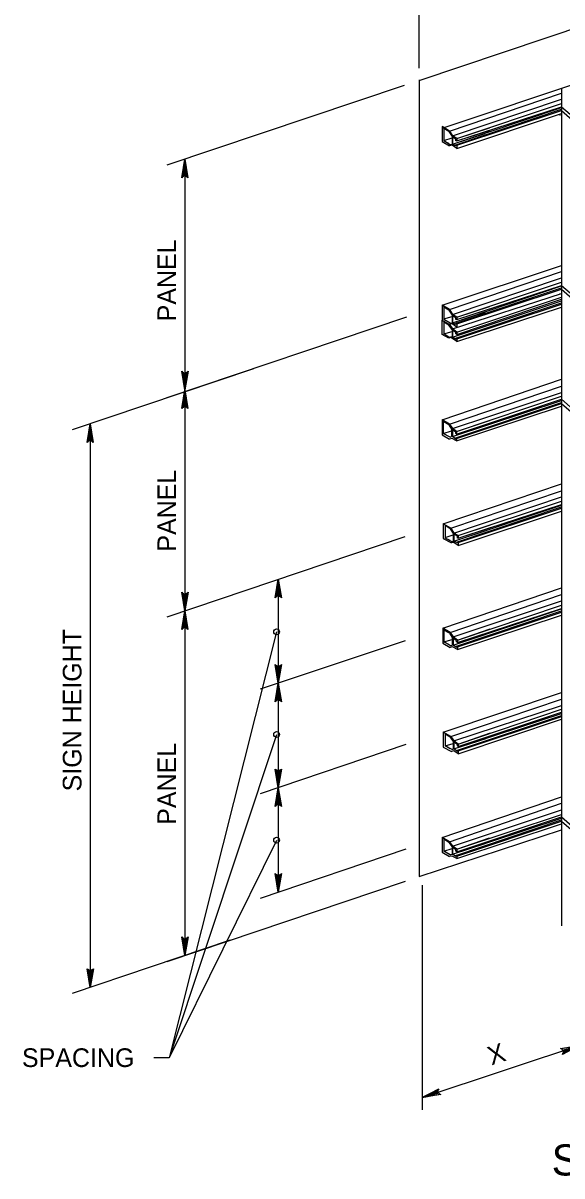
# Model space of a CAD drawing. Extents: x 650495 to 651400, y 297864 to 299646.
# Drawn here: x 650741.8 to 650828.3, y 299357.5 to 299542.7 of the extents above; entities that cross this region are included whole.
import ezdxf

# ---------------------------------------------------------------- set-up
doc = ezdxf.new("R2010")
doc.units = 0
doc.layers.add('2', color=7, linetype='Continuous')
doc.layers.add('3', color=7, linetype='Continuous')

# ---------------------------------------------------------------- blocks, each defined once
blk = doc.blocks.new('RARROW')
at = {"layer": '3'}
blk.add_lwpolyline([(-2.2695, 0.285), (-2.184875, 0.12075), (0, 0), (-2.2695, 0.285), (-2.38575, 0.384625), (0, 0), (-2.183125, -0.108), (-2.262875, -0.2705), (0, 0), (-2.38575, -0.379125), (-2.262875, -0.2705)], dxfattribs=at)

msp = doc.modelspace()

# ---------------------------------------------------------------- linework, layer by layer
at = {"layer": '2'}
for p, q in [((650805.4, 299533.47), (650908.3, 299568.07)), ((650805.4, 299535.47), (650805.4, 299567.07)), ((650809.3, 299525.87), (650904, 299557.67)), ((650803, 299532.67), (650764.9, 299519.87)), ((650805.4, 299533.57), (650805.4, 299405.57)), ((650828.3, 299532.27), (650828.3, 299397.67)), ((650810.3, 299525.37), (650828.3, 299531.47)), ((650810.8, 299524.57), (650828.3, 299530.47)), ((650810.8, 299523.27), (650828.3, 299529.17)), ((650811.3, 299523.17), (650828.3, 299528.87)), ((650811.5, 299524.17), (650828.3, 299529.77)), ((650811.5, 299523.77), (650828.3, 299529.27)), ((650811.5, 299523.07), (650828.3, 299528.67)), ((650828.3, 299529.27), (650832.8, 299525.37)), ((650828.3, 299528.67), (650832.8, 299524.67)), ((650811.5, 299522.57), (650828.3, 299528.17)), ((650828, 299527.97), (650828, 299527.87)), ((650828.3, 299528.17), (650828.3, 299528.17)), ((650809.1, 299526.07), (650809.1, 299526.07)), ((650810.3, 299525.37), (650809.1, 299526.07)), ((650809.1, 299526.07), (650809.1, 299523.67)), ((650809.1, 299526.07), (650810.3, 299525.37)), ((650809.4, 299525.77), (650809.4, 299523.77)), ((650810.2, 299525.27), (650809.4, 299525.77)), ((650810.2, 299525.27), (650810.7, 299524.47)), ((650810.3, 299525.37), (650810.8, 299524.57)), ((650810.8, 299523.27), (650816, 299524.97)), ((650811.5, 299524.17), (650816.7, 299525.87)), ((650811.5, 299523.77), (650816.7, 299525.47)), ((650809.1, 299523.67), (650810.3, 299522.97)), ((650809.4, 299523.87), (650810.7, 299524.27)), ((650810.4, 299523.17), (650809.4, 299523.77)), ((650810.2, 299523.37), (650809.4, 299523.77)), ((650810.7, 299523.07), (650810.3, 299522.97)), ((650810.4, 299523.17), (650810.7, 299523.27)), ((650810.7, 299524.57), (650810.7, 299523.27)), ((650811.5, 299522.57), (650810.7, 299523.07)), ((650811.5, 299524.17), (650810.8, 299524.57)), ((650811.3, 299524.07), (650810.8, 299524.37)), ((650811.3, 299524.07), (650810.8, 299524.37)), ((650810.8, 299524.37), (650810.8, 299523.27)), ((650811.3, 299522.97), (650810.8, 299523.27)), ((650811.3, 299524.07), (650811.3, 299523.87)), ((650811.3, 299523.77), (650811.3, 299524.07)), ((650811.5, 299523.77), (650811.3, 299523.87)), ((650811.5, 299523.77), (650811.3, 299523.77)), ((650811.3, 299523.17), (650811.3, 299522.97)), ((650811.5, 299523.07), (650811.3, 299523.17)), ((650811.3, 299523.17), (650811.3, 299522.97)), ((650811.5, 299523.07), (650811.3, 299523.17)), ((650811.5, 299524.17), (650811.5, 299523.77)), ((650811.5, 299524.17), (650811.5, 299523.77)), ((650811.5, 299523.07), (650811.5, 299522.57)), ((650811.5, 299523.07), (650811.5, 299522.57)), ((650767.8, 299520.87), (650767.8, 299512.47)), ((650767.8, 299520.87), (650767.8, 299483.77)), ((650809.1, 299497.37), (650828.3, 299503.77)), ((650810.3, 299496.67), (650828.3, 299502.77)), ((650810.8, 299495.87), (650828.3, 299501.77)), ((650811.5, 299495.47), (650828.3, 299501.07)), ((650810.8, 299494.57), (650828.3, 299500.47)), ((650810.8, 299493.57), (650828.3, 299499.27)), ((650811.3, 299494.47), (650828.3, 299500.17)), ((650811.5, 299495.07), (650828.3, 299500.57)), ((650811.5, 299494.37), (650828.3, 299499.97)), ((650828, 299499.27), (650828, 299499.17)), ((650828.3, 299500.57), (650832.8, 299496.67)), ((650828.3, 299499.97), (650832.8, 299495.97)), ((650828.3, 299499.47), (650828.3, 299499.47)), ((650810.3, 299496.67), (650809.1, 299497.37)), ((650809.1, 299497.37), (650809.1, 299494.97)), ((650809.1, 299497.37), (650810.3, 299496.67)), ((650809.4, 299497.07), (650809.4, 299495.07)), ((650810.2, 299496.57), (650809.4, 299497.07)), ((650810.8, 299492.27), (650828.3, 299498.07)), ((650811.3, 299492.07), (650828.3, 299497.77)), ((650811.5, 299493.07), (650828.3, 299498.67)), ((650811.5, 299492.67), (650828.3, 299498.37)), ((650811.5, 299491.97), (650828.3, 299497.57)), ((650811.5, 299495.47), (650816.7, 299497.17)), ((650811.5, 299491.57), (650828.3, 299497.07)), ((650803.4, 299495.47), (650764.9, 299482.47)), ((650809.4, 299495.17), (650810.7, 299495.57)), ((650810.2, 299496.57), (650810.7, 299495.77)), ((650810.3, 299496.67), (650810.8, 299495.87)), ((650810.7, 299495.87), (650810.7, 299494.57)), ((650810.8, 299494.57), (650816, 299496.27)), ((650811.5, 299495.47), (650810.8, 299495.87)), ((650811.3, 299495.37), (650810.8, 299495.67)), ((650811.3, 299495.37), (650810.8, 299495.67)), ((650810.8, 299495.67), (650810.8, 299494.57)), ((650811.3, 299495.37), (650811.3, 299495.17)), ((650811.3, 299495.07), (650811.3, 299495.37)), ((650811.5, 299495.07), (650811.3, 299495.17)), ((650811.5, 299495.07), (650816.7, 299496.77)), ((650811.5, 299495.47), (650811.5, 299495.07)), ((650811.5, 299495.47), (650811.5, 299495.07)), ((650809.1, 299492.67), (650809.1, 299494.97)), ((650809.1, 299494.97), (650810.3, 299494.27)), ((650810.4, 299494.47), (650809.4, 299495.07)), ((650810.2, 299494.67), (650809.4, 299495.07)), ((650809.4, 299494.67), (650809.4, 299492.77)), ((650810.2, 299494.17), (650809.4, 299494.67)), ((650810.7, 299493.47), (650810.2, 299494.17)), ((650810.7, 299494.37), (650810.3, 299494.27)), ((650810.3, 299494.27), (650810.8, 299493.57)), ((650810.4, 299494.47), (650810.7, 299494.57)), ((650810.5, 299493.87), (650810.5, 299493.87)), ((650811.5, 299493.87), (650810.7, 299494.37)), ((650810.7, 299493.47), (650810.7, 299492.37)), ((650811.3, 299494.27), (650810.8, 299494.57)), ((650811.5, 299493.07), (650810.8, 299493.57)), ((650811.3, 299492.97), (650810.8, 299493.37)), ((650810.8, 299493.37), (650810.8, 299492.27)), ((650811.5, 299495.07), (650811.3, 299495.07)), ((650811.3, 299494.47), (650811.3, 299494.27)), ((650811.5, 299494.37), (650811.3, 299494.47)), ((650811.3, 299494.47), (650811.3, 299494.27)), ((650811.5, 299494.37), (650811.3, 299494.47)), ((650811.5, 299494.37), (650811.5, 299493.87)), ((650811.5, 299494.37), (650811.5, 299493.87)), ((650810.2, 299492.07), (650809.1, 299492.67)), ((650809.4, 299492.77), (650810.7, 299493.17)), ((650810.2, 299492.27), (650809.4, 299492.77)), ((650810.2, 299492.27), (650810.7, 299492.37)), ((650810.5, 299492.17), (650810.2, 299492.07)), ((650811.5, 299491.57), (650810.5, 299492.17)), ((650811.3, 299491.87), (650810.8, 299492.27)), ((650811.3, 299492.77), (650811.3, 299492.97)), ((650811.5, 299492.67), (650811.3, 299492.77)), ((650811.3, 299492.07), (650811.3, 299491.87)), ((650811.5, 299491.97), (650811.3, 299492.07)), ((650811.5, 299493.07), (650811.5, 299492.67)), ((650811.5, 299491.97), (650811.5, 299491.57)), ((650778.8, 299487.17), (650749.7, 299477.37)), ((650809.1, 299478.97), (650828.3, 299485.47)), ((650810.3, 299478.27), (650828.3, 299484.37)), ((650767.8, 299483.77), (650767.8, 299437.57)), ((650810.8, 299477.57), (650828.3, 299483.37)), ((650811.4, 299477.07), (650828.3, 299482.77)), ((650811.4, 299476.67), (650828.3, 299482.27)), ((650828.3, 299482.27), (650832.8, 299478.27)), ((650810.8, 299476.27), (650828.3, 299482.07)), ((650811.3, 299476.07), (650828.3, 299481.77)), ((650811.4, 299475.97), (650828.3, 299481.57)), ((650811.4, 299475.57), (650828.3, 299481.17)), ((650828.3, 299481.57), (650832.8, 299477.67)), ((650809.1, 299478.97), (650809.1, 299478.97)), ((650810.3, 299478.27), (650809.1, 299478.97)), ((650809.1, 299478.97), (650809.1, 299476.57)), ((650809.1, 299478.97), (650810.3, 299478.27)), ((650809.3, 299478.67), (650809.3, 299476.77)), ((650810.2, 299478.17), (650809.3, 299478.67)), ((650811.4, 299477.07), (650816.7, 299478.87)), ((650752.6, 299478.34), (650752.6, 299432.37)), ((650809.1, 299476.57), (650810.3, 299475.87)), ((650809.3, 299476.77), (650810.6, 299477.17)), ((650810.4, 299476.17), (650809.3, 299476.77)), ((650810.2, 299476.27), (650809.3, 299476.77)), ((650810.2, 299478.17), (650810.6, 299477.47)), ((650810.3, 299478.27), (650810.8, 299477.57)), ((650810.6, 299477.47), (650810.6, 299476.27)), ((650810.8, 299476.27), (650815.9, 299477.97)), ((650811.4, 299477.07), (650810.8, 299477.57)), ((650811.3, 299476.97), (650810.8, 299477.37)), ((650811.3, 299476.97), (650810.8, 299477.37)), ((650810.8, 299477.37), (650810.8, 299476.27)), ((650811.3, 299476.97), (650811.3, 299476.77)), ((650811.3, 299476.77), (650811.3, 299476.97)), ((650811.4, 299476.67), (650811.3, 299476.77)), ((650811.4, 299476.67), (650811.3, 299476.77)), ((650811.4, 299476.67), (650816.7, 299478.37)), ((650811.4, 299477.07), (650811.4, 299476.67)), ((650811.4, 299477.07), (650811.4, 299476.67)), ((650810.7, 299475.97), (650810.3, 299475.87)), ((650810.4, 299476.17), (650810.6, 299476.27)), ((650811.4, 299475.57), (650810.7, 299475.97)), ((650811.3, 299475.87), (650810.8, 299476.27)), ((650811.3, 299476.07), (650811.3, 299475.87)), ((650811.4, 299475.97), (650811.3, 299476.07)), ((650811.3, 299476.07), (650811.3, 299475.87)), ((650811.4, 299475.97), (650811.3, 299476.07)), ((650811.4, 299475.97), (650811.4, 299475.57)), ((650811.4, 299475.97), (650811.4, 299475.57)), ((650809.3, 299462.27), (650828.3, 299468.67)), ((650810.5, 299461.57), (650828.3, 299467.57)), ((650811, 299460.77), (650828.3, 299466.57)), ((650811.7, 299460.37), (650828.3, 299465.87)), ((650811, 299459.47), (650828.3, 299465.27)), ((650811.6, 299459.37), (650828.3, 299464.97)), ((650811.7, 299459.97), (650828.3, 299465.37)), ((650811.7, 299459.27), (650828.3, 299464.77)), ((650811.7, 299458.77), (650828.3, 299464.27)), ((650809.3, 299462.27), (650809.3, 299462.27)), ((650810.5, 299461.57), (650809.3, 299462.27)), ((650809.3, 299462.27), (650809.3, 299459.87)), ((650809.3, 299462.27), (650810.5, 299461.57)), ((650809.6, 299461.97), (650809.6, 299459.97)), ((650810.4, 299461.47), (650809.6, 299461.97)), ((650811.7, 299460.37), (650816.9, 299462.07)), ((650803.1, 299460.17), (650764.9, 299447.27)), ((650809.6, 299460.07), (650810.9, 299460.47)), ((650810.7, 299459.37), (650809.6, 299459.97)), ((650810.4, 299459.57), (650809.6, 299459.97)), ((650810.4, 299461.47), (650810.9, 299460.67)), ((650810.5, 299461.57), (650811, 299460.77)), ((650810.9, 299460.77), (650810.9, 299459.47)), ((650811, 299459.47), (650816.2, 299461.17)), ((650811.7, 299460.37), (650811, 299460.77)), ((650811.6, 299460.27), (650811, 299460.57)), ((650811.6, 299460.27), (650811, 299460.57)), ((650811, 299460.57), (650811, 299459.47)), ((650811.6, 299460.27), (650811.6, 299460.07)), ((650811.6, 299459.97), (650811.6, 299460.27)), ((650811.7, 299459.97), (650811.6, 299460.07)), ((650811.7, 299459.97), (650811.6, 299459.97)), ((650811.7, 299459.97), (650816.9, 299461.67)), ((650811.7, 299460.37), (650811.7, 299459.97)), ((650811.7, 299460.37), (650811.7, 299459.97)), ((650809.3, 299459.87), (650810.6, 299459.17)), ((650811, 299459.27), (650810.6, 299459.17)), ((650810.7, 299459.37), (650810.9, 299459.47)), ((650811.6, 299459.17), (650811, 299459.47)), ((650811.7, 299458.77), (650811, 299459.27)), ((650811.6, 299459.37), (650811.6, 299459.17)), ((650811.7, 299459.27), (650811.6, 299459.37)), ((650811.6, 299459.37), (650811.6, 299459.17)), ((650811.7, 299459.27), (650811.6, 299459.37)), ((650811.7, 299459.27), (650811.7, 299458.77)), ((650811.7, 299459.27), (650811.7, 299458.77)), ((650782.8, 299453.37), (650782.8, 299424.17)), ((650782.8, 299453.31), (650782.8, 299403.07)), ((650809.2, 299445.47), (650828.3, 299451.97)), ((650810.4, 299444.77), (650828.3, 299450.87)), ((650810.9, 299444.07), (650828.3, 299449.87)), ((650811.6, 299443.57), (650828.3, 299449.17)), ((650767.8, 299448.27), (650767.8, 299392.87)), ((650810.9, 299442.77), (650828.3, 299448.57)), ((650811.4, 299442.57), (650828.3, 299448.27)), ((650811.6, 299443.17), (650828.3, 299448.67)), ((650811.6, 299442.47), (650828.3, 299448.07)), ((650811.6, 299442.07), (650828.3, 299447.57)), ((650782.8, 299445.37), (650782.8, 299436.97)), ((650809.2, 299445.47), (650809.2, 299445.47)), ((650810.4, 299444.77), (650809.2, 299445.47)), ((650809.2, 299445.47), (650809.2, 299443.07)), ((650809.2, 299445.47), (650810.4, 299444.77)), ((650809.4, 299445.17), (650809.4, 299443.27)), ((650810.3, 299444.67), (650809.4, 299445.17)), ((650811.6, 299443.57), (650816.8, 299445.37)), ((650782.5, 299444.87), (650765.3, 299376.47)), ((650803.2, 299443.47), (650779.9, 299435.67)), ((650809.4, 299443.27), (650810.7, 299443.67)), ((650810.5, 299442.67), (650809.4, 299443.27)), ((650810.3, 299442.77), (650809.4, 299443.27)), ((650810.3, 299444.67), (650810.7, 299443.97)), ((650810.4, 299444.77), (650810.9, 299444.07)), ((650810.7, 299443.97), (650810.7, 299442.77)), ((650810.9, 299442.77), (650816, 299444.47)), ((650811.6, 299443.57), (650810.9, 299444.07)), ((650811.4, 299443.47), (650810.9, 299443.87)), ((650811.4, 299443.47), (650810.9, 299443.87)), ((650810.9, 299443.87), (650810.9, 299442.77)), ((650811.4, 299443.47), (650811.4, 299443.27)), ((650811.4, 299443.27), (650811.4, 299443.47)), ((650811.6, 299443.17), (650811.4, 299443.27)), ((650811.6, 299443.17), (650811.4, 299443.27)), ((650811.6, 299443.17), (650816.8, 299444.87)), ((650811.6, 299443.57), (650811.6, 299443.17)), ((650811.6, 299443.57), (650811.6, 299443.17)), ((650752.6, 299443.17), (650752.6, 299387.77)), ((650809.2, 299443.07), (650810.4, 299442.37)), ((650810.8, 299442.47), (650810.4, 299442.37)), ((650810.5, 299442.67), (650810.7, 299442.77)), ((650811.6, 299442.07), (650810.8, 299442.47)), ((650811.4, 299442.37), (650810.9, 299442.77)), ((650811.4, 299442.57), (650811.4, 299442.37)), ((650811.6, 299442.47), (650811.4, 299442.57)), ((650811.4, 299442.57), (650811.4, 299442.37)), ((650811.6, 299442.47), (650811.4, 299442.57)), ((650811.6, 299442.47), (650811.6, 299442.07)), ((650811.6, 299442.47), (650811.6, 299442.07)), ((650809.3, 299428.77), (650828.3, 299435.17)), ((650810.5, 299428.07), (650828.3, 299434.07)), ((650811, 299427.37), (650828.3, 299433.07)), ((650811.7, 299426.87), (650828.3, 299432.47)), ((650811, 299426.07), (650828.3, 299431.77)), ((650811.6, 299425.87), (650828.3, 299431.47)), ((650811.7, 299426.47), (650828.3, 299431.97)), ((650811.7, 299425.77), (650828.3, 299431.27)), ((650811.7, 299425.27), (650828.3, 299430.87)), ((650782.8, 299428.67), (650782.8, 299420.27)), ((650809.3, 299428.77), (650809.3, 299428.77)), ((650810.5, 299428.07), (650809.3, 299428.77)), ((650809.3, 299428.77), (650809.3, 299426.37)), ((650809.3, 299428.77), (650810.5, 299428.07)), ((650809.6, 299428.47), (650809.6, 299426.57)), ((650810.4, 299427.97), (650809.6, 299428.47)), ((650811.7, 299426.87), (650816.9, 299428.67)), ((650782.5, 299428.37), (650765.3, 299376.47)), ((650803.3, 299426.77), (650779.9, 299418.87)), ((650809.6, 299426.57), (650810.9, 299426.97)), ((650810.7, 299425.97), (650809.6, 299426.57)), ((650810.4, 299426.07), (650809.6, 299426.57)), ((650810.4, 299427.97), (650810.9, 299427.27)), ((650810.5, 299428.07), (650811, 299427.37)), ((650810.9, 299427.27), (650810.9, 299426.07)), ((650811, 299426.07), (650816.2, 299427.77)), ((650811.7, 299426.87), (650811, 299427.37)), ((650811.6, 299426.77), (650811, 299427.17)), ((650811.6, 299426.77), (650811, 299427.17)), ((650811, 299427.17), (650811, 299426.07)), ((650811.6, 299426.77), (650811.6, 299426.57)), ((650811.6, 299426.57), (650811.6, 299426.77)), ((650811.7, 299426.47), (650811.6, 299426.57)), ((650811.7, 299426.47), (650811.6, 299426.57)), ((650811.7, 299426.47), (650816.9, 299428.17)), ((650811.7, 299426.87), (650811.7, 299426.47)), ((650811.7, 299426.87), (650811.7, 299426.47)), ((650809.3, 299426.37), (650810.6, 299425.67)), ((650811, 299425.77), (650810.6, 299425.67)), ((650810.7, 299425.97), (650810.9, 299426.07)), ((650811.6, 299425.67), (650811, 299426.07)), ((650811.7, 299425.27), (650811, 299425.77)), ((650811.6, 299425.87), (650811.6, 299425.67)), ((650811.7, 299425.77), (650811.6, 299425.87)), ((650811.6, 299425.87), (650811.6, 299425.67)), ((650811.7, 299425.77), (650811.6, 299425.87)), ((650811.7, 299425.77), (650811.7, 299425.27)), ((650811.7, 299425.77), (650811.7, 299425.27)), ((650805.9, 299370.07), (650949.3, 299417.67)), ((650809.1, 299411.87), (650828.3, 299418.37)), ((650810.3, 299411.17), (650828.3, 299417.37)), ((650810.8, 299410.47), (650828.3, 299416.27)), ((650811.5, 299409.97), (650828.3, 299415.57)), ((650810.8, 299409.17), (650828.3, 299414.97)), ((650811.3, 299408.97), (650828.3, 299414.67)), ((650811.5, 299409.57), (650828.3, 299415.17)), ((650811.5, 299408.87), (650828.3, 299414.47)), ((650811.5, 299408.47), (650828.3, 299414.07)), ((650828.3, 299415.17), (650832.8, 299411.17)), ((650828.3, 299414.47), (650832.8, 299410.57)), ((650805.4, 299405.57), (650828.3, 299413.07)), ((650809.1, 299411.87), (650809.1, 299411.87)), ((650810.3, 299411.17), (650809.1, 299411.87)), ((650809.1, 299411.87), (650809.1, 299409.47)), ((650809.1, 299411.87), (650810.3, 299411.17)), ((650811.5, 299409.97), (650816.7, 299411.77)), ((650782.5, 299411.37), (650765.3, 299376.47)), ((650803.3, 299409.97), (650779.9, 299402.07)), ((650809.4, 299411.57), (650809.4, 299409.67)), ((650810.2, 299411.07), (650809.4, 299411.57)), ((650809.4, 299409.67), (650810.7, 299410.07)), ((650810.2, 299411.07), (650810.7, 299410.37)), ((650810.3, 299411.17), (650810.8, 299410.47)), ((650810.7, 299410.37), (650810.7, 299409.17)), ((650810.8, 299409.17), (650816, 299410.87)), ((650811.5, 299409.97), (650810.8, 299410.47)), ((650811.3, 299409.87), (650810.8, 299410.27)), ((650811.3, 299409.87), (650810.8, 299410.27)), ((650810.8, 299410.27), (650810.8, 299409.17)), ((650811.3, 299409.87), (650811.3, 299409.67)), ((650811.3, 299409.67), (650811.3, 299409.87)), ((650811.5, 299409.57), (650816.7, 299411.27)), ((650811.5, 299409.97), (650811.5, 299409.57)), ((650811.5, 299409.97), (650811.5, 299409.57)), ((650809.1, 299409.47), (650810.3, 299408.77)), ((650810.4, 299409.07), (650809.4, 299409.67)), ((650810.2, 299409.17), (650809.4, 299409.67)), ((650810.7, 299408.87), (650810.3, 299408.77)), ((650810.4, 299409.07), (650810.7, 299409.17)), ((650811.5, 299408.47), (650810.7, 299408.87)), ((650811.3, 299408.77), (650810.8, 299409.17)), ((650811.5, 299409.57), (650811.3, 299409.67)), ((650811.5, 299409.57), (650811.3, 299409.67)), ((650811.3, 299408.97), (650811.3, 299408.77)), ((650811.5, 299408.87), (650811.3, 299408.97)), ((650811.3, 299408.97), (650811.3, 299408.77)), ((650811.5, 299408.87), (650811.3, 299408.97)), ((650811.5, 299408.87), (650811.5, 299408.47)), ((650811.5, 299408.87), (650811.5, 299408.47)), ((650803.2, 299404.77), (650764.9, 299391.87)), ((650805.9, 299404.17), (650805.9, 299368.07)), ((650775.1, 299395.37), (650749.7, 299386.77)), ((650765.3, 299376.47), (650762.8, 299376.47)), ((650765.3, 299376.47), (650762.8, 299376.47)), ((650765.3, 299376.47), (650762.8, 299376.47))]:
    msp.add_line(p, q, dxfattribs=at)
for centre in [(650782.53, 299444.9), (650782.53, 299428.41), (650782.53, 299411.41)]:
    msp.add_circle(centre, 0.467, dxfattribs=at)

# ---------------------------------------------------------------- block references
for p, xscale, yscale, rotation in [((650767.8, 299520.87), 1.2574347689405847, 1.3092961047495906, 89.99999999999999), ((650767.8, 299483.77), 1.2574347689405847, 1.3092961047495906, -90.00000000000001), ((650767.8, 299483.77), 1.2574347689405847, 1.3092961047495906, 89.99999999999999), ((650752.6, 299478.34), 1.2574347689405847, 1.3092961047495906, 89.99999999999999), ((650782.8, 299453.37), 1.2574347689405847, 1.3092961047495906, 89.99999999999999), ((650767.8, 299448.27), 1.2574347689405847, 1.3092961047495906, -90.00000000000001), ((650767.8, 299448.27), 1.2574347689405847, 1.3092961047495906, 89.99999999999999), ((650782.8, 299436.64), 1.2574347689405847, 1.3092961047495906, -90.00000000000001), ((650782.8, 299436.64), 1.2574347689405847, 1.3092961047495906, 89.99999999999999), ((650782.8, 299419.85), 1.2574347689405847, 1.3092961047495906, -90.00000000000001), ((650782.8, 299419.85), 1.2574347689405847, 1.3092961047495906, 89.99999999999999), ((650782.8, 299403.07), 1.2574347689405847, 1.3092961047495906, -90.00000000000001), ((650767.8, 299392.87), 1.2574347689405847, 1.3092961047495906, -90.00000000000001), ((650752.6, 299387.77), 1.2574347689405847, 1.3092961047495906, -90.00000000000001), ((650831.1, 299378.43), 1.2574347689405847, 1.3092961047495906, 18.62052730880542), ((650805.9, 299370.07), 1.2574347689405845, 1.3092961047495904, -161.56373355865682)]:
    msp.add_blockref('RARROW', p, dxfattribs=dict(at, xscale=xscale, yscale=yscale, rotation=rotation))

# ---------------------------------------------------------------- texts
for s, rotation, p in [('PANEL', 90, (650766.4, 299494.79)), ('PANEL', 90, (650766.4, 299457.79)), ('SIGN HEIGHT', 90, (650751.2, 299419.26)), ('PANEL', 90, (650766.4, 299413.89)), ('X', 18.3451, (650817.02, 299375.21))]:
    msp.add_text(s, height=3, rotation=rotation, dxfattribs=at).set_placement(p)
for s, height, p in [('SPACING', 3, (650741.64, 299374.97)), ('STIFFENER LOCATION', 5, (650826.7, 299357.54))]:
    msp.add_text(s, height=height, dxfattribs=at).set_placement(p)

doc.saveas('drawing.dxf')
